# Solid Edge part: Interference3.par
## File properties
Last saved by: Administrator
Revision: 51
Accuracy: 0.99
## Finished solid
Body 1: solid body, 4 faces, 4 edges, 2 vertices.
  Faces by surface: cone 2, plane 2
  Edges by curve: circle 2, intersection 1, line 1
Bounding box of the edges (mm): 0.037 x 0.085 x 0.148, from (0.5503, -0.0852, 10.9259) to (0.587, 0, 11.0741).
Conical faces (half-angle, radius in mm at the cone's reference point): 27.3968 deg R0.0554 x2
Planar faces by outward normal: +x 1, oblique 1
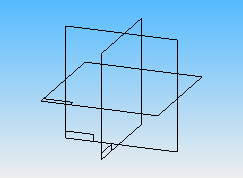
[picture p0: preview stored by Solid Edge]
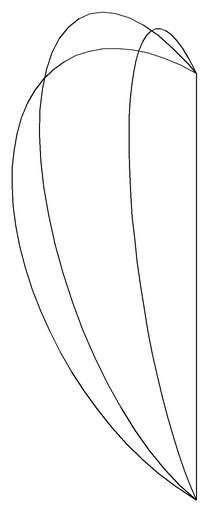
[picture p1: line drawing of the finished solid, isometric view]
